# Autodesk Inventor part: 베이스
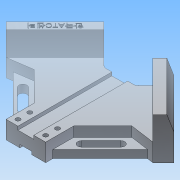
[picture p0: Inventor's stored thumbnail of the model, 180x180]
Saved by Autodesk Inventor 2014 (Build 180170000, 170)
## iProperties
Created: 2020-05
Part Number: 베이스
Material: 알루미늄 6061
Document SubType Name: Modeling
Designer: NET
Mass: 587.924 g
Surface Area: 416.316 cm^2
Volume: 216.946 cm^3
Density: 2.71 g/cm^3
Appearance: 알루미늄 - 평지
Author: NET
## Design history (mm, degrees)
sketch "스케치1"
  geometry: L1 (0, 0)-(120, 0); L2 (120, 0)-(120, 42); L3 (120, 42)-(0, 42); L4 (0, 42)-(0, 0)
  constraints: 8 end point, 2 parallel, 1 horizontal, 1 perpendicular
  dimensions: "d0" = 120 distance of L2.end L3.end; "d1" = 42 distance of L1.end L2.end
extrude "돌출1" new body sketch "스케치1" stored distance "d2" = 120; taper "d3" = 0 deg
chamfer "모따기1" distance "d7" = 40; stored, may be unused: second distance "d8" = 2, angle "d9" = 45 deg
sketch "스케치3"
  geometry: L1 (120, -80)-(80, -120) reference; L2 (0, 0)-(120, 0) reference; L3 (50, -15.65)-(15.65, -50); L4 (0, 0)-(50, 0); L5 (50, 0)-(50, -50); L6 (50, -50)-(0, -50); L7 (0, -50)-(0, 0); 1 further point
  constraints: 10 end point, 3 parallel, 2 point on line, 1 horizontal, 1 perpendicular
  dimensions: "d10" = 95 distance between parallel lines of L1 L3; "d11" = 50 distance of L2.start L4.end; "d12" = 50 distance between parallel lines of L6 L2
extrude "돌출2" cut sketch "스케치3" stored distance "d13" = 120; taper "d14" = 0 deg
sketch "스케치4"
  geometry: L1 (0, 70)-(0, 0) reference; L2 (80, 0)-(0, 0) reference; L3 (120, 40)-(80, 0) reference; L4 (120, 120)-(120, 40) reference; L5 (50, 120)-(120, 120) reference; L6 (15, 105)-(120, 105); L7 (120, 105)-(120, 0); L8 (120, 0)-(15, 0); L9 (15, 0)-(15, 105); 1 further point
  constraints: 8 end point, 2 parallel, 2 point on line, 1 horizontal, 1 perpendicular
  dimensions: "d15" = 15 distance between parallel lines of L6 L5; "d16" = 15 distance between parallel lines of L1 L9
extrude "돌출3" cut sketch "스케치4" distance "d17" = 24; taper "d18" = 0 deg
sketch "스케치5"
  geometry: L1 (0, 42)-(0, 0) reference; L2 (0, 42)-(-15, 42) reference; L3 (-5, 42)-(0, 27); L4 (0, 42)-(0, 27); L5 (-5, 42)-(0, 42); 1 further point
  constraints: 6 end point, 2 point on line, 1 collinear, 1 perpendicular
  dimensions: "d19" = 5 distance of L3.start L1.start; "d20" = 15 distance of L1.start L3.end
extrude "돌출4" cut sketch "스케치5" stored distance "d21" = 24; taper "d22" = 0 deg
sketch "스케치6"
  geometry: L1 (15, 42)-(0, 42) reference; L2 (0, 42)-(0, 0) reference; L3 (0, 42)-(5, 42); L4 (0, 27)-(5, 42); L5 (0, 42)-(0, 27)
  constraints: 6 end point, 2 point on line
  dimensions: "d23" = 5 distance of L1.end L3.end; "d24" = 15 distance of L4.start L1.end
extrude "돌출5" cut sketch "스케치6" stored distance "d25" = 24; taper "d26" = 0 deg
sketch "스케치7"
  geometry: L1 (15.65, 70)-(50, 104.35) reference; L2 (120, 40)-(80, 0) reference; L3 (32.825, 87.175)-(100, 20); L4 (38.482, 92.832)-(105.657, 25.657); L5 (27.168, 81.518)-(94.343, 14.343); L6 (38.482, 92.832)-(27.168, 81.518); L7 (94.343, 14.343)-(105.657, 25.657); 1 further point
  constraints: 10 end point, 2 midpoint, 2 parallel, 1 collinear, 1 perpendicular
  dimensions: "d27" = 8 distance between parallel lines of L4 L3; "d28" = 8 distance between parallel lines of L3 L5
extrude "돌출6" cut sketch "스케치7" distance "d29" = 3.5; taper "d30" = 0 deg
sketch "스케치8"
  geometry: L1 (0, 0)-(56.569, 0) reference; L2 (22.284, 3)-(34.284, 3); L3 (34.284, 3)-(34.284, 0); L4 (34.284, 0)-(22.284, 0); L5 (22.284, 0)-(22.284, 3); 2 further points
  constraints: 8 end point, 2 midpoint, 2 parallel, 1 horizontal, 1 perpendicular
  dimensions: "d31" = 3 distance of L2.end L3.end; "d32" = 12 distance of L3.end L4.end
extrude "돌출7" cut sketch "스케치8" stored distance "d33" = 3.5; taper "d34" = 0 deg
sketch "스케치9"
  geometry: L1 (94.343, 14.343)-(27.168, 81.518) reference; L2 (80, 0)-(15, 0) reference; L3 (15, 0)-(30, 20); L4 (30, 20)-(71.716, 20); L5 (71.716, 20)-(85.858, 5.858); L6 (0, 70)-(15, 70) reference; L7 (15, 70)-(15.65, 70) reference; L8 (15.65, 70)-(27.168, 81.518) reference; L9 (27.168, 81.518)-(94.343, 14.343) reference; L10 (94.343, 14.343)-(80, 0) reference; L11 (80, 0)-(15, 0) reference; L12 (15, 0)-(0, 0) reference; L13 (0, 0)-(0, 70) reference; L14 (15, 70)-(15, 0) reference; L15 (120, 120)-(120, 105) reference; L16 (120, 105)-(120, 40) reference; L17 (120, 40)-(105.657, 25.657) reference; L18 (105.657, 25.657)-(38.482, 92.832) reference; L19 (38.482, 92.832)-(50, 104.35) reference; L20 (50, 104.35)-(50, 105) reference; L21 (50, 105)-(50, 120) reference; L22 (50, 120)-(120, 120) reference; L23 (120, 105)-(50, 105) reference; L24 (38.482, 92.832)-(105.657, 25.657) reference; L25 (27.168, 81.518)-(38.482, 92.832) reference; L26 (94.343, 14.343)-(27.168, 81.518) reference; L27 (105.657, 25.657)-(94.343, 14.343) reference; L28 (32.825, 87.175)-(100, 20); 1 further point
  constraints: 8 end point, 2 midpoint, 2 parallel, 1 point on line
  dimensions: "d35" = 20 distance between parallel lines of L5 L28; "d36" = 20 distance between parallel lines of L2 L4; "d37" = 30 horizontal distance of L12.end L3.end
extrude "돌출8" cut sketch "스케치9" distance "d38" = 10; taper "d39" = 0 deg
node "작업 평면1"
sketch "스케치11"
  geometry: L1 (0, 0)-(0, 70) reference; L2 (0, 70)-(-10, 70) reference; 2 further points
  constraints: 1 other
  dimensions: "d47" = 35 distance from line of L2 point (-5, 35); "d48" = 5 distance from line of point (-5, 35) L1
feature "엠보싱1" sketch "스케치11" dims "d0" = 120, "d1" = 42, "d13" = 120, "d14" = 0, "d49" = 0.5, "d50" = 0
node "작업 평면2"
sketch "스케치15"
  geometry: L1 (0, 65)-(0, 0) reference; L2 (-40, -40)-(-105, -40) reference; L3 (-5, 61.25)-(-5, -5); L4 (-35, -35)-(-101.25, -35); L5 (-34.142, -34.142)-(-40, -40) reference; L6 (0, 0)-(-5.858, -5.858) reference; L7 (-70, 64.35)-(-70, 80) reference; L8 (-70, 80)-(0, 80) reference; L9 (0, 80)-(0, 65) reference; L10 (0, 65)-(-20, 50) reference; L11 (-20, 50)-(-20, 8.284) reference; L12 (-20, 8.284)-(-5.858, -5.858) reference; L13 (0, 0)-(-5.858, -5.858) reference; L14 (0, 65)-(0, 0) reference; L15 (-104.35, 30)-(-70, 64.35) reference; L16 (-120, 30)-(-104.35, 30) reference; L17 (-120, -40)-(-120, 30) reference; L18 (-105, -40)-(-120, -40) reference; L19 (-90, -20)-(-105, -40) reference; L20 (-48.284, -20)-(-90, -20) reference; L21 (-34.142, -34.142)-(-48.284, -20) reference; L22 (-34.142, -34.142)-(-40, -40) reference; L23 (-40, -40)-(-105, -40) reference; L24 (-5.858, -5.858)-(-34.142, -34.142) reference; L25 (-101.25, -35)-(-105, -40); L26 (-105, -40)-(-40, -40); L27 (-35, -35)-(-40, -40); L28 (-5, 61.25)-(0, 65); L29 (0, 65)-(0, 0); L30 (0, 0)-(-5, -5); 1 further point
  constraints: 16 end point, 6 point on line, 5 collinear, 2 parallel
  dimensions: "d66" = 5 distance between parallel lines of L1 L3; "d67" = 5 distance between parallel lines of L2 L4
extrude "돌출12" cut sketch "스케치15" stored distance "d68" = 8; taper "d69" = 0 deg
sketch "스케치18"
  geometry: L1 (120, 0)-(80, 0); L2 (120, 40)-(120, 0); L3 (100, 48.284)-(114.142, 34.142) reference; L4 (114.142, 34.142)-(105.657, 25.657) reference; L5 (105.657, 25.657)-(38.482, 92.832) reference; L6 (38.482, 92.832)-(50, 104.35) reference; L7 (50, 104.35)-(50, 105) reference; L8 (120, 105)-(50, 105) reference; L9 (120, 120)-(120, 105) reference; L10 (50, 120)-(120, 120) reference; L11 (50, 105)-(50, 120) reference; L12 (100, 90)-(100, 48.284) reference; L13 (120, 105)-(100, 90) reference; L14 (0, 70)-(15, 70) reference; L15 (15, 70)-(15.65, 70) reference; L16 (15.65, 70)-(27.168, 81.518) reference; L17 (27.168, 81.518)-(94.343, 14.343) reference; L18 (94.343, 14.343)-(85.858, 5.858) reference; L19 (85.858, 5.858)-(71.716, 20) reference; L20 (71.716, 20)-(30, 20) reference; L21 (30, 20)-(15, 0) reference; L22 (15, 0)-(0, 0) reference; L23 (0, 0)-(0, 70) reference; L24 (15, 70)-(15, 0) reference; L25 (100, 48.284)-(114.142, 34.142) reference; L26 (114.142, 34.142)-(105.657, 25.657) reference; L27 (105.657, 25.657)-(38.482, 92.832) reference; L28 (38.482, 92.832)-(50, 104.35) reference; L29 (50, 104.35)-(50, 105) reference; L30 (120, 105)-(50, 105) reference; L31 (120, 120)-(120, 105) reference; L32 (50, 120)-(120, 120) reference; L33 (50, 105)-(50, 120) reference; L34 (100, 90)-(100, 48.284) reference; L35 (120, 105)-(100, 90) reference; L36 (0, 70)-(15, 70) reference; L37 (15, 70)-(15.65, 70) reference; L38 (15.65, 70)-(27.168, 81.518) reference; L39 (27.168, 81.518)-(94.343, 14.343) reference; L40 (94.343, 14.343)-(85.858, 5.858) reference; L41 (85.858, 5.858)-(71.716, 20) reference; L42 (71.716, 20)-(30, 20) reference; L43 (30, 20)-(15, 0) reference; L44 (15, 0)-(0, 0) reference; L45 (0, 0)-(0, 70) reference; L46 (15, 70)-(15, 0) reference; L47 (120, 40)-(80, 0); L48 (105.657, 25.657)-(94.343, 14.343) reference; 2 further points
  constraints: 6 end point, 2 midpoint, 1 horizontal, 1 horizontal alignment, 1 perpendicular, 1 vertical alignment
  dimensions: "d70" = 40 distance of L2.start L1.start
extrude "돌출13" join sketch "스케치18" distance "d71" = 18; taper "d72" = 0 deg
sketch "스케치19"
  geometry: L1 (80, 0)-(120, 0) reference; L2 (120, 0)-(120, 40) reference; L3 (120, 28.284)-(91.716, 0); L4 (91.716, 0)-(120, 0); L5 (120, 28.284)-(120, 0); 1 further point
  constraints: 6 end point, 1 collinear, 1 point on line
  dimensions: "d73" = 45 deg angle of L1 L3; "d74" = 40 distance of L3.start L3.end; "d75" = 20 distance from line of L3 L1.end
extrude "돌출14" cut sketch "스케치19" stored distance "d76" = 18; taper "d77" = 0 deg
sketch "스케치20"
  geometry: L1 (91.716, 0)-(120, 28.284) reference; L2 (120, 28.284)-(120, 40) reference; L3 (120, 40)-(114.142, 34.142) reference; L4 (114.142, 34.142)-(100, 48.284) reference; L5 (100, 48.284)-(100, 90) reference; L6 (100, 90)-(120, 105) reference; L7 (50, 105)-(120, 105) reference; L8 (50, 104.35)-(50, 105) reference; L9 (38.482, 92.832)-(50, 104.35) reference; L10 (38.482, 92.832)-(105.657, 25.657) reference; L11 (105.657, 25.657)-(94.343, 14.343) reference; L12 (94.343, 14.343)-(27.168, 81.518) reference; L13 (15.65, 70)-(27.168, 81.518) reference; L14 (15, 70)-(15.65, 70) reference; L15 (15, 0)-(15, 70) reference; L16 (15, 0)-(30, 20) reference; L17 (30, 20)-(71.716, 20) reference; L18 (71.716, 20)-(85.858, 5.858) reference; L19 (85.858, 5.858)-(80, 0) reference; L20 (80, 0)-(91.716, 0) reference; L21 (120, 28.284)-(91.716, 0); L22 (50, 92.635)-(27.365, 70); L23 (0, 70)-(15, 70) reference; L24 (15, 70)-(15.65, 70) reference; L25 (15.65, 70)-(27.168, 81.518) reference; L26 (27.168, 81.518)-(94.343, 14.343) reference; L27 (94.343, 14.343)-(105.657, 25.657) reference; L28 (105.657, 25.657)-(38.482, 92.832) reference; L29 (38.482, 92.832)-(50, 104.35) reference; L30 (50, 104.35)-(50, 105) reference; L31 (120, 105)-(50, 105) reference; L32 (120, 105)-(100, 90) reference; L33 (100, 90)-(100, 48.284) reference; L34 (100, 48.284)-(114.142, 34.142) reference; L35 (114.142, 34.142)-(120, 40) reference; L36 (120, 40)-(120, 28.284) reference; L37 (120, 28.284)-(91.716, 0) reference; L38 (91.716, 0)-(80, 0) reference; L39 (80, 0)-(85.858, 5.858) reference; L40 (85.858, 5.858)-(71.716, 20) reference; L41 (71.716, 20)-(30, 20) reference; L42 (30, 20)-(15, 0) reference; L43 (15, 0)-(0, 0) reference; L44 (0, 0)-(0, 70) reference; L45 (15, 70)-(15, 0) reference; L46 (50, 105)-(50, 120) reference; L47 (50, 120)-(120, 120) reference; L48 (120, 120)-(120, 105) reference; L49 (50, 120)-(0, 120); L50 (0, 120)-(0, 70); L51 (27.365, 70)-(0, 70); L52 (50, 92.635)-(50, 120)
  constraints: 12 end point, 3 perpendicular, 2 parallel, 1 horizontal
  dimensions: "d78" = 95 distance between parallel lines of L1 L22
extrude "돌출15" cut sketch "스케치20" stored distance "d79" = 18; taper "d80" = 0 deg
fillet "모깎기1" dims "d81" = 5
sketch "스케치21"
  geometry: L1 (85.858, 5.858)-(80, 0) reference; L2 (80, 0)-(91.716, 0) reference; L3 (120, 28.284)-(120, 40) reference; L4 (120, 40)-(114.142, 34.142) reference; L5 (33.026, 75.66)-(28.83, 71.464) reference; L6 (114.142, 34.142)-(120, 28.284); L7 (85.858, 5.858)-(91.716, 0); 1 further point
  constraints: 4 end point, 1 parallel, 1 perpendicular
extrude "돌출16" cut sketch "스케치21" stored distance "d82" = 18; taper "d83" = 0 deg
sketch "스케치22"
  geometry: L1 (91.716, 0)-(120, 28.284) reference; L2 (105.657, 25.657)-(94.343, 14.343) reference; L3 (100, 20)-(105.858, 14.142); C1 r 2.25 at (83.23, 16.971); C2 r 2.25 at (91.716, 8.485); 1 further point
  constraints: 2 centre point, 2 end point, 2 midpoint
  dimensions: "d84" = 4.5 diameter of C1; "d85" = 4.5 diameter of C2; "d86" = 6 distance from line of C2.centre L1; "d87" = 12 distance of C1.centre C2.centre; "d88" = 14 distance from line of L3 C2.centre; "d89" = 14 distance from line of L3 C1.centre
extrude "돌출17" cut sketch "스케치22" distance "d90" = 8; taper "d91" = 0 deg
node "작업 평면3"
sketch "스케치23"
  geometry: L1 (120, 120)-(120, 105) reference; L2 (120, 105)-(100, 90) reference; L3 (100, 90)-(100, 48.284) reference; L4 (100, 48.284)-(120, 28.284) reference; L5 (120, 28.284)-(91.716, 0) reference; L6 (91.716, 0)-(71.716, 20) reference; L7 (71.716, 20)-(30, 20) reference; L8 (30, 20)-(15, 0) reference; L9 (15, 0)-(0, 0) reference; L10 (0, 0)-(0, 70) reference; L11 (0, 70)-(25.294, 70) reference; L12 (28.83, 71.464)-(48.536, 91.17) reference; L13 (50, 94.706)-(50, 120) reference; L14 (50, 120)-(120, 120) reference; C1 r 2.25 at (83.23, 16.971) reference; C2 r 2.25 at (91.716, 8.485) reference; C3 r 4 at (83.23, 16.971); C4 r 4 at (91.716, 8.485); A1 r 5 centre (25.294, 75) between (25.294, 70) and (28.83, 71.464) reference; A2 r 5 centre (45, 94.706) between (48.536, 91.17) and (50, 94.706) reference; 1 further point
  constraints: 2 centre point, 2 coincident
  dimensions: "d93" = 8 diameter of C3; "d94" = 8 diameter of C4
extrude "돌출18" cut sketch "스케치23" stored distance "d95" = 8; taper "d96" = 0 deg
sketch "스케치24"
  geometry: L1 (20, 71.716)-(20, 56.716) reference; L2 (20, 56.716)-(15, 52.966) reference; L3 (15, 52.966)-(15, -13.284) reference; L4 (15, -13.284)-(14.142, -14.142) reference; L5 (0, 0)-(14.142, -14.142) reference; L6 (0, 41.716)-(0, 0) reference; L7 (15, 52.966)-(0, 41.716) reference; L8 (-50, 71.716)-(20, 71.716) reference; L9 (-50, 46.421)-(-50, 71.716) reference; L10 (-71.17, 23.18)-(-51.464, 42.886) reference; L11 (-100, 21.716)-(-74.706, 21.716) reference; L12 (-100, -48.284)-(-100, 21.716) reference; L13 (-85, -48.284)-(-100, -48.284) reference; L14 (-81.25, -43.284)-(-85, -48.284) reference; L15 (-15, -43.284)-(-81.25, -43.284) reference; L16 (-14.142, -42.426)-(-15, -43.284) reference; L17 (-14.142, -42.426)-(-28.284, -28.284) reference; L18 (-28.284, -28.284)-(-70, -28.284) reference; L19 (-70, -28.284)-(-81.25, -43.284) reference; L20 (14.142, -14.142)-(20, -20) reference; L21 (20, -20)-(-8.284, -48.284) reference; L22 (-8.284, -48.284)-(-14.142, -42.426) reference; L23 (15, -13.284)-(15, -15); L24 (-15, -43.284)-(-13.284, -43.284); C1 r 4 at (-16.77, -31.314) reference; C2 r 4 at (-8.284, -39.799) reference; A1 r 5 centre (-55, 46.421) between (-51.464, 42.886) and (-50, 46.421) reference; A2 r 5 centre (-74.706, 26.716) between (-74.706, 21.716) and (-71.17, 23.18) reference; 1 further point
  constraints: 4 end point, 2 perpendicular, 2 point on line
extrude "돌출19" join sketch "스케치24" distance "d97" = 8; taper "d98" = 0 deg
sketch "스케치25"
  geometry: L1 (91.716, 0)-(120, 28.284) reference; L2 (105.657, 25.657)-(94.343, 14.343) reference; L3 (94.343, 14.343)-(100.201, 8.485); L4 (105.657, 25.657)-(111.515, 19.799); 1 further point
  constraints: 4 end point, 2 perpendicular, 2 point on line
extrude "돌출20" cut sketch "스케치25" distance "d99" = 3.5; taper "d100" = 0 deg
sketch "스케치27"
  geometry: L1 (18.75, 5)-(86.716, 5) reference; L2 (38, 12)-(66, 12); L3 (38, 8)-(66, 8); L4 (66, 16)-(38, 16); L5 (0, 0)-(0, 70) reference; A1 r 4 centre (38, 12) between (38, 16) and (38, 8); A2 r 4 centre (66, 12) between (66, 8) and (66, 16); 2 further points
  constraints: 8 end point, 4 point on circle, 4 tangent, 2 centre point, 2 parallel, 1 midpoint
  dimensions: "d101" = 28 distance of L2.start L2.end; "d104" = 8 distance between parallel lines of L3 L4; "d105" = 7 distance between parallel lines of L1 L2; "d106" = 38 distance from line of L5 L2.start
extrude "돌출21" cut sketch "스케치27" stored distance "d107" = 3.5; taper "d108" = 0 deg
sketch "스케치28"
  geometry: L1 (40, 0)-(0, 0) reference; L2 (14, 3)-(26, 3); L3 (26, 3)-(26, 0); L4 (26, 0)-(14, 0); L5 (14, 0)-(14, 3); 2 further points
  constraints: 8 end point, 2 midpoint, 2 parallel, 1 horizontal, 1 perpendicular
  dimensions: "d109" = 12 distance of L3.end L4.end; "d110" = 3 distance of L2.end L3.end
extrude "돌출22" cut sketch "스케치28" stored distance "d111" = 3.5; taper "d112" = 0 deg
node "솔리드1"
mirror "대칭1"
mirror "대칭4"
mirror "대칭5"
node "투영된 루프1"
node "투영된 루프4"
node "절단 모서리 투영1"
node "절단 모서리 투영4"
node "절단 모서리 투영6"
node "절단 모서리 투영7"
node "절단 모서리 투영8"
node "절단 모서리 투영9"
node "절단 모서리 투영10"
other parameters: "d60" = -8, "d92" = -8
